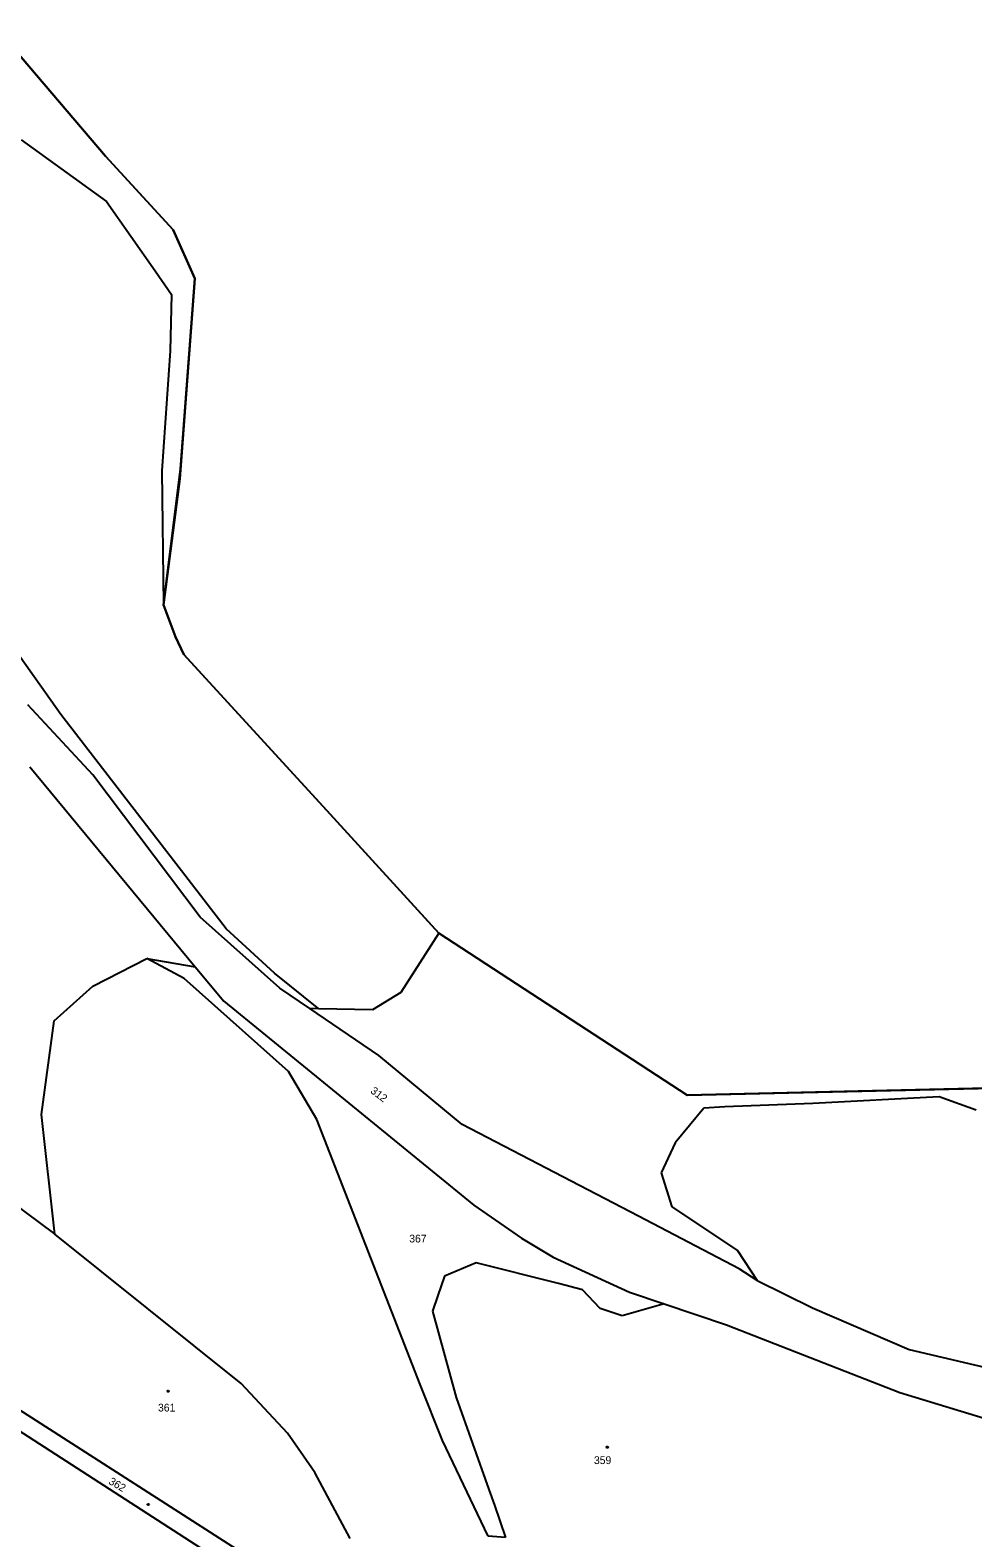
# Model space of a CAD drawing. Extents: x -841286 to -834997, y -1020681 to -1017810.
# Drawn here: x -836292.8 to -836086.8, y -1019500.9 to -1019171.2 of the extents above; entities that cross this region are included whole.
import ezdxf

# ---------------------------------------------------------------- set-up
doc = ezdxf.new("R2010")
doc.units = 0
for name, color, linetype in [('OVNE_POP', 7, 'Continuous'), ('OVNE_PRE', 7, 'Continuous'), ('OVNE_SET', 7, 'Continuous'), ('OVNI_SET', 7, 'Continuous')]:
    doc.layers.add(name, color=color, linetype=linetype)

msp = doc.modelspace()

# ---------------------------------------------------------------- linework, layer by layer
at = {"layer": 'OVNE_POP'}
for points in [[(-836262.55, -1019468.69), (-836262.46, -1019468.84), (-836262.55, -1019468.99), (-836262.73, -1019468.99), (-836262.82, -1019468.84), (-836262.73, -1019468.69)], [(-836166.59, -1019480.93), (-836166.5, -1019481.08), (-836166.59, -1019481.23), (-836166.77, -1019481.23), (-836166.86, -1019481.08), (-836166.77, -1019480.93)], [(-836266.82, -1019493.51), (-836266.83, -1019493.69), (-836266.99, -1019493.76), (-836267.14, -1019493.67), (-836267.13, -1019493.49), (-836266.97, -1019493.42)]]:
    msp.add_lwpolyline(points, close=True, dxfattribs=at)
at = {"layer": 'OVNE_SET'}
for p, q in [((-836299.83, -1019171.25), (-836276.3, -1019198.81)), ((-836294.77, -1019195.2), (-836276.08, -1019208.74)), ((-836276.3, -1019198.81), (-836261.56, -1019214.92)), ((-836276.08, -1019208.74), (-836265.51, -1019223.89)), ((-836261.56, -1019214.92), (-836256.84, -1019225.58)), ((-836265.51, -1019223.89), (-836261.91, -1019229.04)), ((-836256.84, -1019225.58), (-836260.07, -1019269.34)), ((-836261.91, -1019229.04), (-836262.21, -1019241.34)), ((-836262.21, -1019241.34), (-836264, -1019267.57)), ((-836264, -1019267.57), (-836263.68, -1019296.88)), ((-836260.07, -1019269.34), (-836263.68, -1019296.88)), ((-836263.68, -1019296.88), (-836261.06, -1019303.93)), ((-836261.06, -1019303.93), (-836259.21, -1019307.72)), ((-836286.13, -1019320.89), (-836296.17, -1019306.66)), ((-836259.21, -1019307.72), (-836227.25, -1019342.66)), ((-836279.11, -1019334.09), (-836293.3, -1019318.73)), ((-836258.98, -1019356.02), (-836286.13, -1019320.89)), ((-836292.85, -1019332.3), (-836256.71, -1019376.01)), ((-836255.65, -1019365.17), (-836279.11, -1019334.09)), ((-836227.25, -1019342.66), (-836203.48, -1019368.66)), ((-836249.95, -1019367.71), (-836258.98, -1019356.02)), ((-836238.25, -1019380.7), (-836255.65, -1019365.17)), ((-836239.42, -1019377.45), (-836249.95, -1019367.71)), ((-836203.48, -1019368.66), (-836211.83, -1019381.68)), ((-836203.48, -1019368.66), (-836149.25, -1019404.08)), ((-836279.1, -1019380.3), (-836267.28, -1019374.2)), ((-836267.28, -1019374.2), (-836256.71, -1019376.01)), ((-836259.18, -1019378.59), (-836267.28, -1019374.2)), ((-836236.33, -1019398.9), (-836259.18, -1019378.59)), ((-836256.71, -1019376.01), (-836250.49, -1019383.54)), ((-836229.69, -1019385.2), (-836239.42, -1019377.45)), ((-836287.56, -1019387.85), (-836279.1, -1019380.3)), ((-836231.69, -1019385.16), (-836238.25, -1019380.7)), ((-836211.83, -1019381.68), (-836217.98, -1019385.42)), ((-836250.49, -1019383.54), (-836195.84, -1019428.18)), ((-836229.69, -1019385.2), (-836231.69, -1019385.16)), ((-836216.62, -1019395.41), (-836231.69, -1019385.16)), ((-836217.98, -1019385.42), (-836229.69, -1019385.2)), ((-836290.29, -1019408.34), (-836287.56, -1019387.85)), ((-836198.39, -1019410.54), (-836216.62, -1019395.41)), ((-836230.19, -1019409.39), (-836236.33, -1019398.9)), ((-836149.25, -1019404.08), (-836049.52, -1019401.8)), ((-836331.16, -1019402), (-836287.37, -1019434.52)), ((-836094.15, -1019404.45), (-836121.77, -1019405.96)), ((-836086.06, -1019407.39), (-836094.15, -1019404.45)), ((-836287.37, -1019434.52), (-836290.29, -1019408.34)), ((-836145.58, -1019406.93), (-836151.88, -1019414.49)), ((-836141.01, -1019406.65), (-836145.58, -1019406.93)), ((-836121.77, -1019405.96), (-836141.01, -1019406.65)), ((-836207.54, -1019467.37), (-836230.19, -1019409.39)), ((-836159.9, -1019430.59), (-836198.39, -1019410.54)), ((-836151.88, -1019414.49), (-836154.93, -1019421.05)), ((-836154.93, -1019421.05), (-836152.59, -1019428.54)), ((-836195.84, -1019428.18), (-836185.43, -1019435.39)), ((-836137.85, -1019442.08), (-836159.9, -1019430.59)), ((-836152.59, -1019428.54), (-836138.22, -1019438.05)), ((-836246.7, -1019467.17), (-836287.37, -1019434.52)), ((-836185.43, -1019435.39), (-836178.51, -1019439.52)), ((-836138.22, -1019438.05), (-836133.96, -1019444.62)), ((-836195.31, -1019440.74), (-836202.26, -1019443.69)), ((-836177.36, -1019445.29), (-836195.31, -1019440.74)), ((-836178.51, -1019439.52), (-836161.81, -1019447.14)), ((-836202.26, -1019443.69), (-836203.71, -1019447.91)), ((-836133.96, -1019444.62), (-836137.85, -1019442.08)), ((-836133.96, -1019444.62), (-836121.83, -1019450.59)), ((-836203.71, -1019447.91), (-836204.88, -1019451.35)), ((-836172.12, -1019446.63), (-836177.36, -1019445.29)), ((-836168.27, -1019450.74), (-836172.12, -1019446.63)), ((-836161.81, -1019447.14), (-836154.28, -1019449.69)), ((-836163.46, -1019452.32), (-836168.27, -1019450.74)), ((-836154.28, -1019449.69), (-836163.46, -1019452.32)), ((-836154.28, -1019449.69), (-836140.62, -1019454.32)), ((-836121.83, -1019450.59), (-836100.7, -1019459.72)), ((-836204.88, -1019451.35), (-836199.73, -1019470.2)), ((-836140.62, -1019454.32), (-836102.74, -1019469.13)), ((-836100.7, -1019459.72), (-836077.61, -1019465.18)), ((-836304.19, -1019467.12), (-836219.03, -1019521.71)), ((-836236.55, -1019477.99), (-836246.7, -1019467.17)), ((-836202.67, -1019479.58), (-836207.54, -1019467.37)), ((-836305.32, -1019470.91), (-836236.46, -1019515.39)), ((-836199.73, -1019470.2), (-836192.6, -1019490.31)), ((-836102.74, -1019469.13), (-836074.81, -1019477.66)), ((-836233.06, -1019483.02), (-836236.55, -1019477.99)), ((-836192.75, -1019500.53), (-836202.67, -1019479.58)), ((-836230.58, -1019486.57), (-836233.06, -1019483.02)), ((-836222.9, -1019501), (-836230.58, -1019486.57)), ((-836192.6, -1019490.31), (-836191.34, -1019493.78)), ((-836191.34, -1019493.78), (-836188.9, -1019500.78)), ((-836188.9, -1019500.78), (-836192.75, -1019500.53))]:
    msp.add_line(p, q, dxfattribs=at)
at = {"layer": 'OVNI_SET'}
msp.add_lwpolyline([(-836049.52, -1019401.8), (-836149.25, -1019404.08), (-836203.48, -1019368.66), (-836227.25, -1019342.66), (-836259.21, -1019307.72), (-836261.06, -1019303.93), (-836263.68, -1019296.88), (-836259.91, -1019267.19), (-836256.84, -1019225.58), (-836261.56, -1019214.92), (-836276.3, -1019198.81), (-836299.83, -1019171.25)], dxfattribs=at)

# ---------------------------------------------------------------- texts
at = {"layer": 'OVNE_PRE'}
for s, rotation, p in [('312', 322.8617, (-836218.59, -1019403.47)), ('362', 329.5653, (-836275.8, -1019489))]:
    msp.add_text(s, height=1.7, rotation=rotation, dxfattribs=at).set_placement(p)
for s, p in [('367', (-836209.96, -1019436.31)), ('361', (-836264.86, -1019473.27)), ('359', (-836169.6, -1019484.76))]:
    msp.add_text(s, height=1.7, dxfattribs=at).set_placement(p)

doc.saveas('drawing.dxf')
